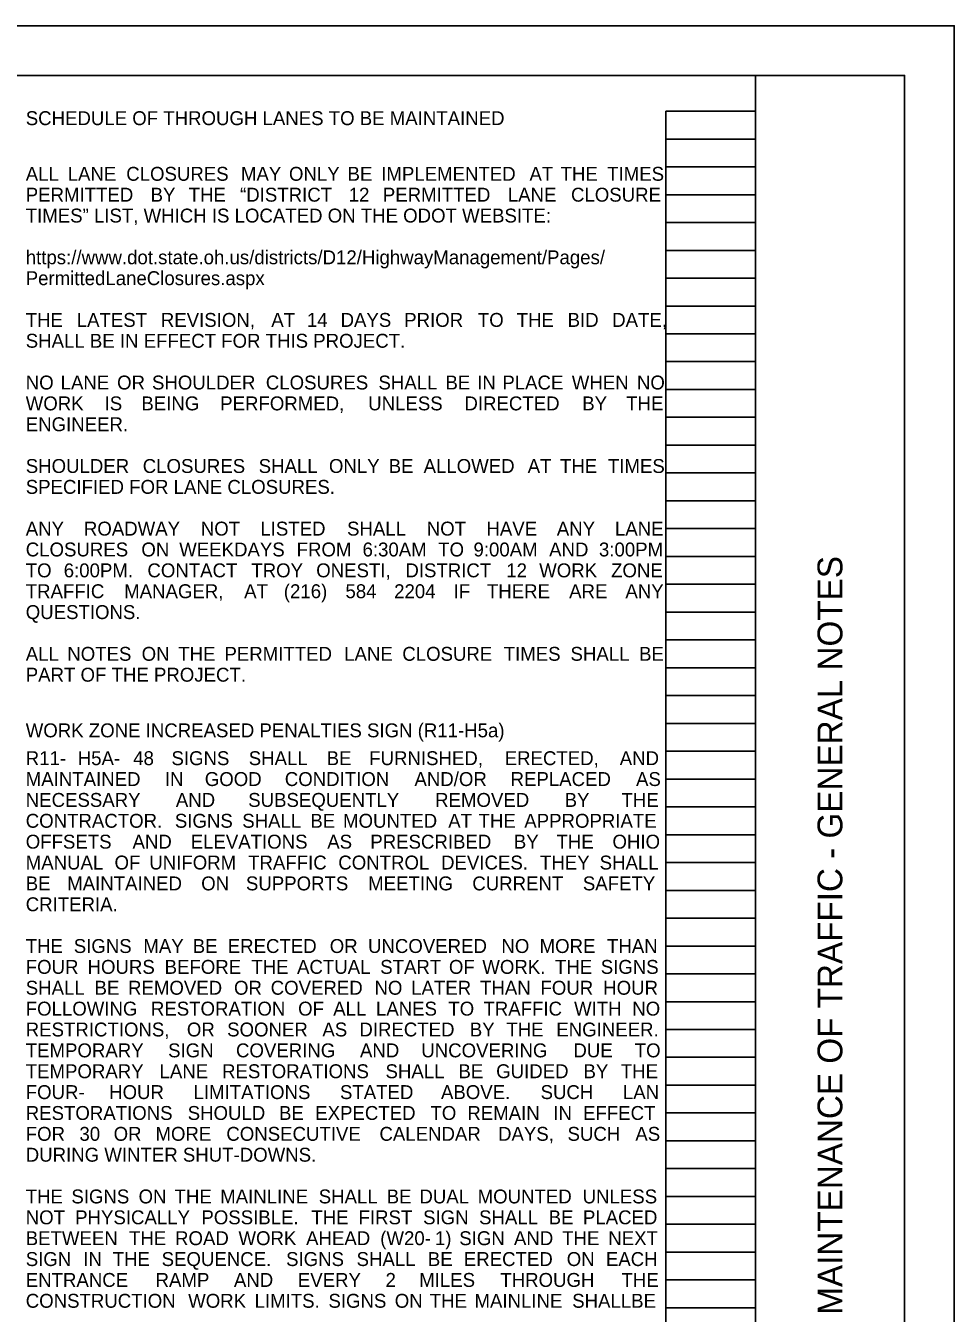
# Model space of a CAD drawing. Extents: x 0 to 43.6, y -18 to 22.
# Drawn here: x 24.66 to 34, y 9.04 to 22 of the extents above; entities that cross this region are included whole.
import ezdxf

# ---------------------------------------------------------------- set-up
doc = ezdxf.new("R2010")
doc.units = 0
for name, color, linetype in [('SH_Border', 7, 'Continuous'), ('SH_Cut_Line', 7, 'Continuous'), ('SH_Data', 7, 'Continuous'), ('SH_Text', 7, 'Continuous')]:
    doc.layers.add(name, color=color, linetype=linetype)

msp = doc.modelspace()

# ---------------------------------------------------------------- linework, layer by layer
at = {"layer": 'SH_Border'}
msp.add_line((32, 0.5), (32, 21.5), dxfattribs=at)
msp.add_lwpolyline([(1.5, 21.5), (33.5, 21.5), (33.5, 0.5), (1.5, 0.5)], close=True, dxfattribs=at)
at = {"layer": 'SH_Cut_Line'}
msp.add_lwpolyline([(0, 0), (34, 0), (34, 22), (0, 22)], close=True, dxfattribs=at)
at = {"layer": 'SH_Data'}
for p, q in [((31.1, 0.98), (31.1, 21.14)), ((31.1, 21.14), (32, 21.14)), ((32, 0.98), (32, 21.14)), ((31.1, 20.86), (32, 20.86)), ((31.1, 20.58), (32, 20.58)), ((31.1, 20.3), (32, 20.3)), ((31.1, 20.02), (32, 20.02)), ((31.1, 19.74), (32, 19.74)), ((31.1, 19.46), (32, 19.46)), ((31.1, 19.18), (32, 19.18)), ((31.1, 18.9), (32, 18.9)), ((31.1, 18.62), (32, 18.62)), ((31.1, 18.34), (32, 18.34)), ((31.1, 18.06), (32, 18.06)), ((31.1, 17.78), (32, 17.78)), ((31.1, 17.5), (32, 17.5)), ((31.1, 17.22), (32, 17.22)), ((31.1, 16.94), (32, 16.94)), ((31.1, 16.66), (32, 16.66)), ((31.1, 16.38), (32, 16.38)), ((31.1, 16.1), (32, 16.1)), ((31.1, 15.82), (32, 15.82)), ((31.1, 15.54), (32, 15.54)), ((31.1, 15.26), (32, 15.26)), ((31.1, 14.98), (32, 14.98)), ((31.1, 14.7), (32, 14.7)), ((31.1, 14.42), (32, 14.42)), ((31.1, 14.14), (32, 14.14)), ((31.1, 13.86), (32, 13.86)), ((31.1, 13.58), (32, 13.58)), ((31.1, 13.3), (32, 13.3)), ((31.1, 13.02), (32, 13.02)), ((31.1, 12.74), (32, 12.74)), ((31.1, 12.46), (32, 12.46)), ((31.1, 12.18), (32, 12.18)), ((31.1, 11.9), (32, 11.9)), ((31.1, 11.62), (32, 11.62)), ((31.1, 11.34), (32, 11.34)), ((31.1, 11.06), (32, 11.06)), ((31.1, 10.78), (32, 10.78)), ((31.1, 10.5), (32, 10.5)), ((31.1, 10.22), (32, 10.22)), ((31.1, 9.94), (32, 9.94)), ((31.1, 9.66), (32, 9.66)), ((31.1, 9.38), (32, 9.38)), ((31.1, 9.1), (32, 9.1))]:
    msp.add_line(p, q, dxfattribs=at)

# ---------------------------------------------------------------- texts
msp.add_text('MAINTENANCE OF TRAFFIC - GENERAL NOTES', height=0.25, rotation=90, dxfattribs=at).set_placement((32.875, 9.03))
at = {"layer": 'SH_Text'}
for s, p in [('SCHEDULE OF THROUGH LANES TO BE MAINTAINED', (24.66, 21)), ('ALL ', (24.66, 20.44)), ('LANE ', (25.082, 20.44)), ('CLOSURES ', (25.671, 20.44)), ('MAY ', (26.825, 20.44)), ('ONLY ', (27.308, 20.44)), ('BE ', (27.897, 20.44)), ('IMPLEMENTED ', (28.236, 20.44)), ('AT ', (29.727, 20.44)), ('THE ', (30.04, 20.44)), ('TIMES ', (30.509, 20.44)), ('PERMITTED ', (24.66, 20.23)), ('BY ', (25.916, 20.23)), ('THE ', (26.299, 20.23)), ('“DISTRICT ', (26.816, 20.23)), ('12 ', (27.909, 20.23)), ('PERMITTED ', (28.252, 20.23)), ('LANE ', (29.509, 20.23)), ('CLOSURE ', (30.145, 20.23)), ('TIMES” LIST, WHICH IS LOCATED ON THE ODOT WEBSITE:', (24.66, 20.02)), ('https://www.dot.state.oh.us/districts/D12/HighwayManagement/Pages/', (24.66, 19.6)), ('PermittedLaneClosures.aspx', (24.66, 19.39)), ('THE ', (24.66, 18.97)), ('LATEST ', (25.173, 18.97)), ('REVISION, ', (26.019, 18.97)), ('AT ', (27.13, 18.97)), ('14 ', (27.488, 18.97)), ('DAYS ', (27.827, 18.97)), ('PRIOR ', (28.467, 18.97)), ('TO ', (29.208, 18.97)), ('THE ', (29.598, 18.97)), ('BID ', (30.111, 18.97)), ('DATE, ', (30.559, 18.97)), ('SHALL BE IN EFFECT FOR THIS PROJECT.', (24.66, 18.76)), ('NO ', (24.66, 18.34)), ('LANE ', (25.011, 18.34)), ('OR ', (25.579, 18.34)), ('SHOULDER ', (25.93, 18.34)), ('CLOSURES ', (27.075, 18.34)), ('SHALL ', (28.208, 18.34)), ('BE ', (28.882, 18.34)), ('IN ', (29.201, 18.34)), ('PLACE ', (29.454, 18.34)), ('WHEN ', (30.153, 18.34)), ('NO ', (30.808, 18.34)), ('WORK ', (24.66, 18.13)), ('IS ', (25.453, 18.13)), ('BEING ', (25.823, 18.13)), ('PERFORMED, ', (26.616, 18.13)), ('UNLESS ', (28.105, 18.13)), ('DIRECTED ', (29.073, 18.13)), ('BY ', (30.258, 18.13)), ('THE ', (30.7, 18.13)), ('ENGINEER.', (24.66, 17.92)), ('SHOULDER ', (24.66, 17.5)), ('CLOSURES ', (25.837, 17.5)), ('SHALL ', (27.003, 17.5)), ('ONLY ', (27.71, 17.5)), ('BE ', (28.311, 17.5)), ('ALLOWED ', (28.662, 17.5)), ('AT ', (29.709, 17.5)), ('THE ', (30.034, 17.5)), ('TIMES ', (30.516, 17.5)), ('SPECIFIED FOR LANE CLOSURES. ', (24.66, 17.29)), ('ANY ', (24.66, 16.87)), ('ROADWAY ', (25.245, 16.87)), ('NOT ', (26.421, 16.87)), ('LISTED ', (27.02, 16.87)), ('SHALL ', (27.892, 16.87)), ('NOT ', (28.694, 16.87)), ('HAVE ', (29.294, 16.87)), ('ANY ', (30.002, 16.87)), ('LANE ', (30.587, 16.87)), ('CLOSURES ', (24.66, 16.66)), ('ON ', (25.823, 16.66)), ('WEEKDAYS ', (26.204, 16.66)), ('FROM ', (27.385, 16.66)), ('6:30AM ', (28.048, 16.66)), ('TO ', (28.809, 16.66)), ('9:00AM ', (29.164, 16.66)), ('AND ', (29.925, 16.66)), ('3:00PM ', (30.426, 16.66)), ('TO ', (24.66, 16.45)), ('6:00PM. ', (25.042, 16.45)), ('CONTACT ', (25.884, 16.45)), ('TROY ', (26.929, 16.45)), ('ONESTI, ', (27.582, 16.45)), ('DISTRICT ', (28.479, 16.45)), ('12 ', (29.494, 16.45)), ('WORK ', (29.825, 16.45)), ('ZONE ', (30.548, 16.45)), ('TRAFFIC ', (24.66, 16.24)), ('MANAGER, ', (25.65, 16.24)), ('AT ', (26.857, 16.24)), ('(216) ', (27.256, 16.24)), ('584 ', (27.876, 16.24)), ('2204 ', (28.366, 16.24)), ('IF ', (28.965, 16.24)), ('THERE ', (29.299, 16.24)), ('ARE ', (30.126, 16.24)), ('ANY ', (30.692, 16.24)), ('QUESTIONS.', (24.66, 16.03)), ('ALL ', (24.66, 15.61)), ('NOTES ', (25.078, 15.61)), ('ON ', (25.826, 15.61)), ('THE ', (26.194, 15.61)), ('PERMITTED ', (26.659, 15.61)), ('LANE ', (27.863, 15.61)), ('CLOSURE ', (28.448, 15.61)), ('TIMES ', (29.468, 15.61)), ('SHALL ', (30.14, 15.61)), ('BE ', (30.83, 15.61)), ('PART OF THE PROJECT.', (24.66, 15.4)), ('WORK ZONE INCREASED PENALTIES SIGN (R11-H5a)', (24.66, 14.84)), ('R11-', (24.66, 14.56)), ('H5A-', (25.183, 14.56)), ('48 ', (25.741, 14.56)), ('SIGNS ', (26.126, 14.56)), ('SHALL ', (26.903, 14.56)), ('BE ', (27.687, 14.56)), ('FURNISHED, ', (28.115, 14.56)), ('ERECTED, ', (29.478, 14.56)), ('AND', (30.635, 14.56)), ('MAINTAINED ', (24.66, 14.35)), ('IN ', (26.059, 14.35)), ('GOOD ', (26.461, 14.35)), ('CONDITION ', (27.266, 14.35)), ('AND/OR ', (28.57, 14.35)), ('REPLACED ', (29.537, 14.35)), ('AS', (30.799, 14.35)), ('NECESSARY ', (24.66, 14.14)), ('AND ', (26.17, 14.14)), ('SUBSEQUENTLY ', (26.898, 14.14)), ('REMOVED ', (28.778, 14.14)), ('BY ', (30.081, 14.14)), ('THE', (30.653, 14.14)), ('CONTRACTOR. ', (24.66, 13.93)), ('SIGNS ', (26.16, 13.93)), ('SHALL ', (26.838, 13.93)), ('BE ', (27.523, 13.93)), ('MOUNTED ', (27.852, 13.93)), ('AT ', (28.91, 13.93)), ('THE ', (29.215, 13.93)), ('APPROPRIATE', (29.675, 13.93)), ('OFFSETS ', (24.66, 13.72)), ('ELEVATIONS ', (26.319, 13.72)), ('AS ', (27.693, 13.72)), ('PRESCRIBED ', (28.126, 13.72)), ('OHIO ', (30.562, 13.72)), ('AND ', (25.734, 13.72)), ('BY ', (29.57, 13.72)), ('THE ', (29.999, 13.72)), ('MANUAL ', (24.66, 13.51)), ('OF ', (25.553, 13.51)), ('UNIFORM ', (25.903, 13.51)), ('TRAFFIC ', (26.897, 13.51)), ('CONTROL ', (27.804, 13.51)), ('DEVICES. ', (28.838, 13.51)), ('THEY ', (29.833, 13.51)), ('SHALL ', (30.433, 13.51)), ('BE ', (24.66, 13.3)), ('MAINTAINED ', (25.077, 13.3)), ('ON ', (26.425, 13.3)), ('SUPPORTS ', (26.875, 13.3)), ('MEETING ', (28.104, 13.3)), ('CURRENT ', (29.152, 13.3)), ('SAFETY ', (30.264, 13.3)), ('CRITERIA.', (24.66, 13.09)), ('THE ', (24.66, 12.67)), ('SIGNS ', (25.143, 12.67)), ('MAY ', (25.843, 12.67)), ('BE ', (26.34, 12.67)), ('ERECTED ', (26.692, 12.67)), ('OR ', (27.718, 12.67)), ('UNCOVERED ', (28.103, 12.67)), ('NO ', (29.445, 12.67)), ('MORE ', (29.829, 12.67)), ('THAN', (30.507, 12.67)), ('FOUR ', (24.66, 12.46)), ('HOURS ', (25.282, 12.46)), ('BEFORE ', (26.057, 12.46)), ('THE ', (26.93, 12.46)), ('ACTUAL ', (27.389, 12.46)), ('START ', (28.226, 12.46)), ('OF ', (28.917, 12.46)), ('WORK. ', (29.253, 12.46)), ('THE ', (29.984, 12.46)), ('SIGNS', (30.444, 12.46)), ('SHALL ', (24.66, 12.25)), ('BE ', (25.352, 12.25)), ('REMOVED ', (25.689, 12.25)), ('OR ', (26.755, 12.25)), ('COVERED ', (27.124, 12.25)), ('NO ', (28.168, 12.25)), ('LATER ', (28.537, 12.25)), ('THAN ', (29.23, 12.25)), ('FOUR ', (29.838, 12.25)), ('HOUR', (30.469, 12.25)), ('FOLLOWING ', (24.66, 12.04)), ('RESTORATION ', (25.919, 12.04)), ('OF ', (27.4, 12.04)), ('ALL ', (27.753, 12.04)), ('LANES ', (28.183, 12.04)), ('TO ', (28.911, 12.04)), ('TRAFFIC ', (29.264, 12.04)), ('WITH ', (30.176, 12.04)), ('NO', (30.761, 12.04)), ('RESTRICTIONS, ', (24.66, 11.83)), ('OR ', (26.281, 11.83)), ('SOONER ', (26.686, 11.83)), ('AS ', (27.644, 11.83)), ('DIRECTED ', (28.016, 11.83)), ('BY ', (29.127, 11.83)), ('THE ', (29.495, 11.83)), ('ENGINEER.', (29.997, 11.83)), ('TEMPORARY ', (24.66, 11.62)), ('SIGN ', (26.092, 11.62)), ('COVERING ', (26.775, 11.62)), ('AND ', (28.022, 11.62)), ('UNCOVERING ', (28.639, 11.62)), ('DUE ', (30.169, 11.62)), ('TO', (30.786, 11.62)), ('TEMPORARY ', (24.66, 11.41)), ('LANE ', (26.006, 11.41)), ('RESTORATIONS ', (26.635, 11.41)), ('SHALL ', (28.279, 11.41)), ('BE ', (29.013, 11.41)), ('GUIDED ', (29.392, 11.41)), ('BY ', (30.271, 11.41)), ('THE', (30.646, 11.41)), ('FOUR-', (24.66, 11.2)), ('HOUR ', (25.499, 11.2)), ('LIMITATIONS ', (26.348, 11.2)), ('STATED ', (27.821, 11.2)), ('ABOVE. ', (28.837, 11.2)), ('SUCH ', (29.839, 11.2)), ('LAN', (30.667, 11.2)), ('RESTORATIONS ', (24.66, 10.99)), ('SHOULD ', (26.289, 10.99)), ('BE ', (27.208, 10.99)), ('EXPECTED ', (27.572, 10.99)), ('TO ', (28.731, 10.99)), ('REMAIN ', (29.102, 10.99)), ('IN ', (29.967, 10.99)), ('EFFECT ', (30.266, 10.99)), ('FOR ', (24.66, 10.78)), ('30 ', (25.2, 10.78)), ('OR ', (25.544, 10.78)), ('MORE ', (25.965, 10.78)), ('CONSECUTIVE ', (26.678, 10.78)), ('CALENDAR ', (28.218, 10.78)), ('DAYS, ', (29.411, 10.78)), ('SUCH ', (30.11, 10.78)), ('AS', (30.792, 10.78)), ('DURING WINTER SHUT-DOWNS.', (24.66, 10.57)), ('THE ', (24.66, 10.15)), ('SIGNS ', (25.119, 10.15)), ('ON ', (25.795, 10.15)), ('THE ', (26.157, 10.15)), ('MAINLINE ', (26.616, 10.15)), ('SHALL ', (27.607, 10.15)), ('BE ', (28.291, 10.15)), ('DUAL ', (28.62, 10.15)), ('MOUNTED ', (29.206, 10.15)), ('UNLESS', (30.262, 10.15)), ('NOT ', (24.66, 9.94)), ('PHYSICALLY ', (25.157, 9.94)), ('POSSIBLE. ', (26.427, 9.94)), ('THE ', (27.533, 9.94)), ('FIRST ', (28.008, 9.94)), ('SIGN ', (28.657, 9.94)), ('SHALL ', (29.22, 9.94)), ('BE ', (29.92, 9.94)), ('PLACED', (30.265, 9.94)), ('BETWEEN ', (24.66, 9.73)), ('THE ', (25.699, 9.73)), ('ROAD ', (26.162, 9.73)), ('WORK ', (26.8, 9.73)), ('AHEAD ', (27.48, 9.73)), ('(W20-', (28.226, 9.73)), ('1) ', (28.776, 9.73)), ('SIGN ', (29.021, 9.73)), ('AND ', (29.571, 9.73)), ('THE ', (30.056, 9.73)), ('NEXT', (30.52, 9.73)), ('SIGN ', (24.66, 9.52)), ('IN ', (25.239, 9.52)), ('THE ', (25.535, 9.52)), ('SEQUENCE. ', (26.027, 9.52)), ('SIGNS ', (27.279, 9.52)), ('SHALL ', (27.988, 9.52)), ('BE ', (28.705, 9.52)), ('ERECTED ', (29.067, 9.52)), ('ON ', (30.102, 9.52)), ('EACH', (30.496, 9.52)), ('ENTRANCE ', (24.66, 9.31)), ('RAMP ', (25.966, 9.31)), ('AND ', (26.754, 9.31)), ('EVERY ', (27.397, 9.31)), ('2 ', (28.279, 9.31)), ('MILES ', (28.618, 9.31)), ('THROUGH ', (29.434, 9.31)), ('THE', (30.653, 9.31)), ('CONSTRUCTION ', (24.66, 9.1)), ('WORK ', (26.294, 9.1)), ('LIMITS. ', (26.962, 9.1)), ('SIGNS ', (27.705, 9.1)), ('ON ', (28.372, 9.1)), ('THE ', (28.724, 9.1)), ('MAINLINE ', (29.174, 9.1)), ('SHALLBE ', (30.157, 9.1))]:
    msp.add_text(s, height=0.14, dxfattribs=at).set_placement(p)

doc.saveas('drawing.dxf')
